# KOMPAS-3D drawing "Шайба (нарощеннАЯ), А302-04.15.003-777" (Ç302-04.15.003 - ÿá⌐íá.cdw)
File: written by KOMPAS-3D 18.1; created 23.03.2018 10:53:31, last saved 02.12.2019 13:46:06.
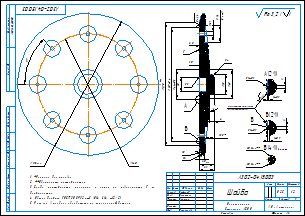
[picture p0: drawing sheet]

Sheet 1: A3, landscape

Document properties: Автор: Милов; Параметр неуказанной шероховатости: Ra 3,2; Полное имя файла: ..\3Д ПВХ\А302-01.15.003 - Шайба.m3d; Масса: 0.247573; Организация: Милов

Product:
- Part/product: Шайба (нарощеннАЯ)  | designation А302-04.15.003-777
    Материал: Полипропилен  ГОСТ 26996-86 (density 900 kg/m3)
    Масса: 0.432773
    Раздел спецификации: Детали
    Форматы листов документа: A4
    source file: А302-04.15.003-777 - Шайба.cdw
- Part/product: Шайба  | designation А302-02.15.003
    Материал: Полипропилен  ГОСТ 26996-86 (density 900 kg/m3)
    Масса: 0.251914
    Раздел спецификации: Детали
    Форматы листов документа: A4
- Part/product: Шайба  | designation А302-01.15.003
    Масса: 0.292092
    Раздел спецификации: Детали
    Форматы листов документа: A4
- Part/product: Шайба  | designation А302-03.15.003
    Материал: Полипропилен  ГОСТ 26996-86 (density 900 kg/m3)
    Масса: 0.28231
    Раздел спецификации: Детали
    Форматы листов документа: A4
    source file: ..\Чертежи Полипропилен\А302-03.15.003 - Шайба.cdw
- Part/product: Шайба  | designation А302-05.15.003
    Материал: Поливинилхлорид (density 0 kg/m3)
    Раздел спецификации: Детали
    Форматы листов документа: A4
    source file: ..\Чертежи ПВХ\А302-02.15.003 - Шайба.cdw, ..\Чертежи Полипропилен\А302-03.15.003 - Шайба.cdw, А302-04.15.003 - Шайба.cdw
  - Body: Тело 10
      Масса: 0.249827
- Part/product: Шайба  | designation А302-04.15.003
    Материал: Полипропилен  ГОСТ 26996-86 (density 900 kg/m3)
    Масса: 0.247573
    Раздел спецификации: Детали
    Форматы листов документа: A4

Title block, sheet 1: Наименование: Шайба; designation: А302-04.15.003; Материал: Полипропилен / Стержень  200; Масса: 0,25; scale: 1:2; Количество листов документа: 1; organisation: АО «Астерион»; Форматы листов документа: A3; stored path: \\192.168.87.28\Konstructor_doc\Мембранные насосы\Мембранный электропривод\А302-00.00.000 - ASTRA-302 (МЭ200)\Чертежи\А302-00.15.003 - Шайба.cdw; Разработал: Лифлянд; Проверил: Борисенко; Т. контр.: Лучихин; Утвердил: Григорьева

Views: Вид 1, Местный разрез 1, Спереди, Выносной элемент 3, Выносной элемент 4, Выносной элемент 5, Выносной элемент А, Выносной элемент, Выносной элемент Б, Выносной элемент В
Referenced files in D:\Мембранные насосы\Мембранный электропривод\А302-00.00.000 - ASTRA-302 (МЭ200)\3Д ПВХ\: А302-01.15.003 - Шайба.m3d
Referenced files in Z:\Мембранные насосы\Мембранный электропривод\А302-00.00.000 - ASTRA-302 (МЭ200)\3Д\: А302-00.15.003 - Шайба.m3d
Referenced files in Z:\Мембранные насосы\Мембранный электропривод\А302-00.00.000 - ASTRA-302 (МЭ200)\3Д ПВХ\: А302-01.15.003 - Шайба.m3d
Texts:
  Ra 1,6
  Зона контакта с мембраной
  поверхность глянцевая
  Ra 0,80
  Ra 3,2
  Ra 3,2 ( )
Dimensions and other numbers on the sheet: 6,5; 40; 28; 4; 6; 20; 3; 10; 13,5; 41±0,3; 157±0,4; 7; 170; 2; 5; 24; 8 отв.; 21; 1±0,1; 0,5; 1:2; 0,25

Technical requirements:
  *Размеры для справок.
  **Обеспечить инструментом.
  Следы инструмента, царапины и риски на поверхности  Г  не
  допускаются.
  Общие допуски ГОСТ 30893.2-mK (H14, h14,  t2/2).
  Размеры в скобках обработать по сопрягаемой детали.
